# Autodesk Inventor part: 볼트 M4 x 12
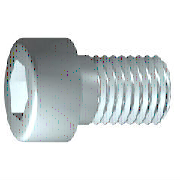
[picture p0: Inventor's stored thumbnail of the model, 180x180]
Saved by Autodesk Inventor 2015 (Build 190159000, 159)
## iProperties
IsCustomPart: 0
Created: 2012-02
Part Number: 볼트 M4 x 12
Material: 강철, 연강
Description: 6각 소켓 머리 캡 나사
Document SubType Name: Modeling
Standard: ISO 4762
Designer: mduedu
Standard Revision: Fourth edition 2004-03-01
Standards Organization: ISO
Language: ko-KR
Size Designation: M4 x 12
Categories: <MemberInstance><Categories><Category DisplayName="조임쇠" InternalName="e4da775c-781d-43d5-af7c-5136215cf5a6" Mnemonic="FSTN"><Category DisplayName="볼트" InternalN
Density: 7.86 g/cm^3
Mass: 2.23465 g
Surface Area: 3.30853 cm^2
Volume: 0.284306 cm^3
Appearance: 강철
Author: mduedu
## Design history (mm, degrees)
sketch "스케치1"
  geometry: L1 (-1, 0)-(12, 0); L2 (12, 0)-(12, 2); L3 (12, 2)-(1.75, 2); L4 (1.75, 2)-(1.32, 2); L5 (1.32, 2)-(0, 2); L6 (0, 2)-(0, 3.5); L7 (0, 3.5)-(-4, 3.5); L8 (-4, 3.5)-(-4, 1.732); L9 (-4, 1.732)-(-2, 1.732); L10 (-2, 1.732)-(-1, 0); L11 (-7.2, 0)-(15.2, 0) reference; L12 (0, -0.7)-(0, 4.2) reference; L13 (1.75, 2)-(0, 2)
  constraints: 22 end point, 6 parallel, 2 collinear, 2 perpendicular, 1 horizontal, 1 point on line
  dimensions: "d1" = 10.25 distance from line of L3.end L2 (= GEL); "d2" = 0.42952 distance of L4.end L3.end (computed from GAL); "d3" = 4 distance between parallel lines of L8 L6 (= KOH); "d4" = 2 distance of L8.end L9.end (= INTI); "d5" = 60 deg angle of L10 L1; "d6" = 4 diameter of L3 L1 (= GD); "d7" = 4 diameter of L5 L1 (= BDM); "d8" = 3.4641 diameter of L9 L1 (= 1.1547 x SW); "d9" = 7 diameter of L7 L1 (= KOD); "d26" = 12 distance between parallel lines of L12 L2 (= NLG)
revolve "본체" sketch "스케치1" stored, may be unused: angle "d10" = 90 deg
sketch "스케치2"
  geometry: L1 (0, -4.9)-(0, 4.9) reference; L2 (-4.9, 0)-(4.9, 0) reference; L3 (1.732, 0)-(0.866, -1.5); L4 (0.866, -1.5)-(-0.866, -1.5); L5 (-0.866, -1.5)-(-1.732, 0); L6 (-1.732, 0)-(-0.866, 1.5); L7 (-0.866, 1.5)-(0.866, 1.5); L8 (0.866, 1.5)-(1.732, 0); 2 further points
  constraints: 12 end point, 1 coincident, 1 horizontal alignment, 1 point on line, 12 other
extrude "슬롯" join sketch "스케치2" stored distance "d11" = 10; taper "d12" = 0 deg
workplane "Work Plane1"
fillet "Fillet2" dims "d30" = 0.1 (= R)
body "Solid1"
fillet "모깎기1" dims "d17" = 0.4 (= RR)
feature "스레드" dims "d13" = 10.25 (= GEL), "d14" = 0
chamfer "모따기1" distance "d15" = 0.42941 (= -0.5 x SPD + 0.5 x GD); stored, may be unused: second distance "d16" = 0.42941 (= GUL), angle "d27" = 45 deg
other parameters: "GD" = 4 [user parameter; used in 2 equation terms], "NLG" = 12 [user parameter; used in 1 equation term], "GEL" = 10.25 [user parameter; used in 2 equation terms], "KOD" = 7 [user parameter; used in 1 equation term], "KOH" = 4 [user parameter; used in 1 equation term], "INTI" = 2 [user parameter; used in 1 equation term], "GAL" = 0.42941 (= 0.61345 x PTC) [user parameter; used in 1 equation term], "GUL" = 0.42941 (= 0.61345 x PTC) [user parameter; used in 1 equation term], "BDM" = 4 (= NND) [user parameter; used in 1 equation term], "SW" = 3 [user parameter; used in 2 equation terms], "RR" = 0.4 [user parameter; used in 1 equation term], "SPD" = 3.14117 (= NND - 1.2269 x PTC) [user parameter; used in 1 equation term], "d19" = 0, "d28" = 0, "d29" = 0, "R" = 0.1 [user parameter; used in 1 equation term], "TOA" = 30 deg [user parameter], "GD1" = 3.14117 (= THREADDIA - 1.2269 x PTC) [user parameter], "THREADDIA" = 4 [user parameter; used in 1 equation term], "FAWI" = 45 deg [user parameter], "TPU" = 14.28571 (computed from PTC) [user parameter], "PTC" = 0.7 [user parameter; used in 5 equation terms], "NND" = 4 [user parameter; used in 2 equation terms], "E0" = 3.465 (= 1.155 x SW) [user parameter]
